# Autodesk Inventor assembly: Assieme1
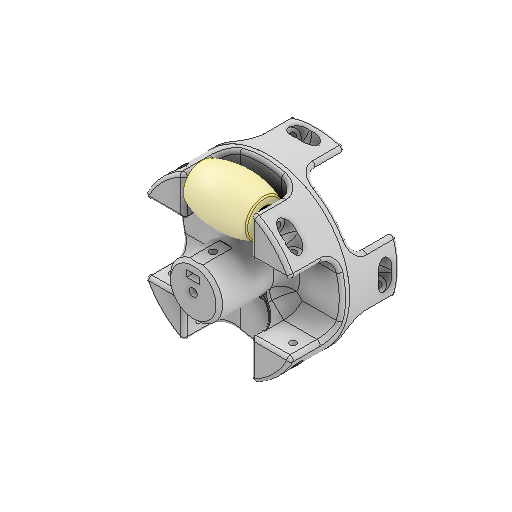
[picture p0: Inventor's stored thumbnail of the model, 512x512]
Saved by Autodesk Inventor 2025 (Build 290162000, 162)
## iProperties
Created: 2025-05
Part Number: Assieme1
Document SubType Name: Assembly
Designer: R5800u
Author: R5800u
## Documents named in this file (5)
- C:\Users\R5800u\Desktop\mecanum7\Assieme1.iam
- C:\Users\R5800u\Desktop\mecanum7\Parte1c.ipt
- C:\Users\R5800u\Desktop\mecanum7\Parte1a.ipt
- C:\Users\R5800u\Desktop\mecanum6\nema17_pancake.iam
- C:\Users\R5800u\Desktop\mecanum6\rullo.ipt
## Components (4 placed, 4 different names)
1. Parte1c:1 — Coincidente:1, Coincidente:2, Angolo:1
2. Parte1a:1 — Coincidente:1, Coincidente:2, Angolo:1, Rotazionale:1, Angolo:2, Coincidente:3, Coincidente:4
3. nema17_pancake:1 [sub-assembly] — Rotazionale:1, Angolo:2
4. rullo:1 — Coincidente:3, Coincidente:4
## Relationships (7: Mate 4, Angle 2, RevoluteJoint 1)
- Coincidente:1 [Mate]: Parte1c:1 ↔ Parte1a:1
- Coincidente:2 [Mate]: Parte1c:1 ↔ Parte1a:1
- Angolo:1 [Angle]: Parte1c:1 ↔ Parte1a:1
- Rotazionale:1 [RevoluteJoint]: Parte1a:1 ↔ nema17_pancake:1
- Angolo:2 [Angle]: Parte1a:1 ↔ nema17_pancake:1
- Coincidente:3 [Mate]: Parte1a:1 ↔ rullo:1
- Coincidente:4 [Mate]: Parte1a:1 ↔ rullo:1
